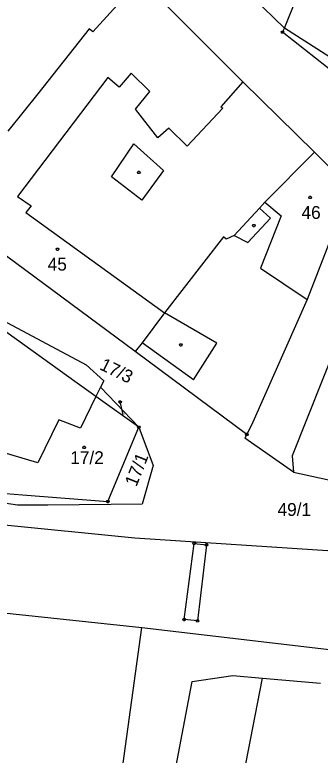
# Model space of a CAD drawing. Extents: x -634640 to -629202, y -1196156 to -1190068.
# Drawn here: x -631402.3 to -631362, y -1192622.8 to -1192525.3 of the extents above; entities that cross this region are included whole.
import ezdxf

# ---------------------------------------------------------------- set-up
doc = ezdxf.new("R2010")
doc.units = 0
for name, color, linetype in [('Vrstva 1', 7, 'Continuous'), ('Vrstva 2', 7, 'Continuous'), ('Vrstva 3', 7, 'Continuous'), ('Vrstva 4', 7, 'Continuous'), ('Vrstva 5', 7, 'Continuous'), ('Vrstva 7', 7, 'Continuous'), ('Vrstva 8', 7, 'Continuous')]:
    doc.layers.add(name, color=color, linetype=linetype)

msp = doc.modelspace()

# ---------------------------------------------------------------- linework, layer by layer
at = {"layer": 'Vrstva 1'}
for p, q in [((-631366.72, -1192527.02), (-631363.92, -1192519.95)), ((-631385.7, -1192520.6), (-631391.98, -1192527.48)), ((-631385.7, -1192520.6), (-631372.23, -1192534.1)), ((-631366.72, -1192527.02), (-631370.95, -1192522.92)), ((-631392.47, -1192527.12), (-631399.24, -1192535.68)), ((-631391.98, -1192527.48), (-631392.47, -1192527.12)), ((-631360.28, -1192531.15), (-631366.72, -1192527.02)), ((-631372.23, -1192534.1), (-631362.77, -1192543.35)), ((-631399.24, -1192535.68), (-631403.21, -1192540.6)), ((-631362.77, -1192543.35), (-631369.31, -1192549.91)), ((-631362.77, -1192543.35), (-631358.09, -1192548.08)), ((-631358.09, -1192548.08), (-631363.74, -1192562.75)), ((-631369.31, -1192549.91), (-631370.03, -1192550.7)), ((-631370.03, -1192550.7), (-631373.35, -1192554.34)), ((-631386.43, -1192569.6), (-631410.65, -1192551.66)), ((-631374.79, -1192554.5), (-631382.54, -1192564.5)), ((-631374.41, -1192554.8), (-631374.79, -1192554.5)), ((-631373.35, -1192554.34), (-631374.41, -1192554.8)), ((-631363.74, -1192562.75), (-631370.89, -1192578.9)), ((-631394.07, -1192573.75), (-631408.55, -1192563.37)), ((-631408.43, -1192563.08), (-631392.89, -1192571.37)), ((-631357.63, -1192562.92), (-631365.7, -1192583.34)), ((-631382.54, -1192564.5), (-631385.51, -1192568.47)), ((-631385.51, -1192568.47), (-631386.43, -1192569.6)), ((-631371.7, -1192580.51), (-631386.43, -1192569.6)), ((-631392.89, -1192571.37), (-631390.56, -1192573.48)), ((-631390.56, -1192573.48), (-631390.99, -1192574.3)), ((-631391.58, -1192575.53), (-631394.07, -1192573.75)), ((-631390.99, -1192574.3), (-631391.58, -1192575.53)), ((-631390.99, -1192574.3), (-631385.93, -1192579.57)), ((-631391.58, -1192575.53), (-631393.63, -1192579.68)), ((-631385.93, -1192579.57), (-631391.58, -1192575.53)), ((-631396.46, -1192578.6), (-631399.25, -1192584.24)), ((-631393.63, -1192579.68), (-631396.46, -1192578.6)), ((-631370.89, -1192578.9), (-631371.7, -1192580.51)), ((-631399.25, -1192584.24), (-631415.08, -1192579.62)), ((-631390.01, -1192589.37), (-631385.93, -1192579.57)), ((-631385.93, -1192579.57), (-631384.02, -1192584.62)), ((-631371.7, -1192580.51), (-631371.96, -1192581.02)), ((-631365.55, -1192585.49), (-631371.96, -1192581.02)), ((-631365.7, -1192583.34), (-631365.55, -1192585.49)), ((-631384.02, -1192584.62), (-631385.48, -1192589.72)), ((-631365.55, -1192585.49), (-631353.37, -1192588.16)), ((-631413.23, -1192587.56), (-631401.28, -1192588.49)), ((-631401.91, -1192589.82), (-631410.57, -1192588.53)), ((-631401.28, -1192588.49), (-631390.01, -1192589.37)), ((-631397.9, -1192589.84), (-631401.91, -1192589.82)), ((-631385.48, -1192589.72), (-631397.9, -1192589.84)), ((-631386.46, -1192594.17), (-631416.15, -1192591.27)), ((-631355.77, -1192596.21), (-631386.46, -1192594.17)), ((-631412.23, -1192603.12), (-631385.52, -1192605.93)), ((-631390.28, -1192640.16), (-631385.52, -1192605.93)), ((-631385.52, -1192605.93), (-631353.37, -1192609.74)), ((-631378.89, -1192613.08), (-631373.54, -1192612.25)), ((-631373.54, -1192612.25), (-631369.61, -1192612.61)), ((-631371.82, -1192623.91), (-631369.61, -1192612.61)), ((-631369.61, -1192612.61), (-631361.99, -1192613.3)), ((-631387.27, -1192657.24), (-631378.89, -1192613.08))]:
    msp.add_line(p, q, dxfattribs=at)
msp.add_lwpolyline([(-631358.1, -1192533.83), (-631358.31, -1192534.41), (-631367, -1192527.54), (-631366.72, -1192527.02)], dxfattribs=at)
at = {"layer": 'Vrstva 3'}
msp.add_lwpolyline([(-631393.03, -1192582.08), (-631392.94, -1192582.23), (-631393.03, -1192582.38), (-631393.21, -1192582.38), (-631393.3, -1192582.23), (-631393.21, -1192582.08), (-631393.03, -1192582.08)], dxfattribs=at)
at = {"layer": 'Vrstva 4'}
for p, q in [((-631390, -1192533.49), (-631401.92, -1192549.18)), ((-631388.51, -1192534.78), (-631390, -1192533.49)), ((-631386.96, -1192532.96), (-631388.51, -1192534.78)), ((-631384.47, -1192535.37), (-631386.96, -1192532.96)), ((-631372.23, -1192534.1), (-631375.11, -1192537.36)), ((-631386.35, -1192537.69), (-631384.47, -1192535.37)), ((-631374.85, -1192537.53), (-631379.54, -1192542.57)), ((-631375.11, -1192537.36), (-631374.85, -1192537.53)), ((-631383.42, -1192541.44), (-631386.35, -1192537.69)), ((-631381.97, -1192540.17), (-631383.42, -1192541.44)), ((-631379.54, -1192542.57), (-631381.97, -1192540.17)), ((-631389.53, -1192546.59), (-631386.6, -1192542.24)), ((-631386.6, -1192542.24), (-631382.69, -1192545.74)), ((-631382.69, -1192545.74), (-631385.52, -1192549.66)), ((-631385.52, -1192549.66), (-631389.53, -1192546.59)), ((-631401.92, -1192549.18), (-631400.12, -1192550.42)), ((-631369.31, -1192549.91), (-631367.17, -1192551.71)), ((-631400.12, -1192550.42), (-631400.82, -1192551.28)), ((-631368.57, -1192552.03), (-631370.03, -1192550.7)), ((-631400.82, -1192551.28), (-631382.54, -1192564.5)), ((-631371.58, -1192555.25), (-631368.57, -1192552.03)), ((-631367.17, -1192551.71), (-631369.91, -1192558.62)), ((-631373.35, -1192554.34), (-631371.58, -1192555.25)), ((-631369.91, -1192558.62), (-631363.74, -1192562.75)), ((-631375.63, -1192568.49), (-631382.54, -1192564.5)), ((-631378.72, -1192573.34), (-631385.51, -1192568.47)), ((-631378.72, -1192573.34), (-631375.63, -1192568.49)), ((-631379.97, -1192604.91), (-631378.64, -1192594.87)), ((-631378.64, -1192594.87), (-631377.02, -1192595.05)), ((-631377.02, -1192595.05), (-631378.21, -1192605.07)), ((-631378.21, -1192605.07), (-631379.97, -1192604.91))]:
    msp.add_line(p, q, dxfattribs=at)
for points in [[(-631378.515, -1192594.993), (-631378.683, -1192595.045), (-631378.807, -1192594.922), (-631378.765, -1192594.747), (-631378.597, -1192594.695), (-631378.473, -1192594.818), (-631378.515, -1192594.993)], [(-631377.104, -1192595.204), (-631377.2, -1192595.057), (-631377.116, -1192594.904), (-631376.936, -1192594.896), (-631376.84, -1192595.043), (-631376.924, -1192595.196), (-631377.104, -1192595.204)], [(-631379.885, -1192604.757), (-631379.79, -1192604.904), (-631379.875, -1192605.057), (-631380.055, -1192605.063), (-631380.15, -1192604.916), (-631380.065, -1192604.763), (-631379.885, -1192604.757)], [(-631378.31, -1192604.926), (-631378.136, -1192604.906), (-631378.036, -1192605.05), (-631378.11, -1192605.214), (-631378.284, -1192605.234), (-631378.384, -1192605.09), (-631378.31, -1192604.926)]]:
    msp.add_lwpolyline(points, dxfattribs=at)
at = {"layer": 'Vrstva 5'}
for points in [[(-631385.83, -1192545.86), (-631385.74, -1192546.01), (-631385.83, -1192546.16), (-631386.01, -1192546.16), (-631386.1, -1192546.01), (-631386.01, -1192545.86), (-631385.83, -1192545.86)], [(-631363.26, -1192549.16), (-631363.17, -1192549.31), (-631363.26, -1192549.46), (-631363.44, -1192549.46), (-631363.53, -1192549.31), (-631363.44, -1192549.16), (-631363.26, -1192549.16)], [(-631370.68, -1192552.86), (-631370.59, -1192553.01), (-631370.68, -1192553.16), (-631370.86, -1192553.16), (-631370.95, -1192553.01), (-631370.86, -1192552.86), (-631370.68, -1192552.86)], [(-631396.56, -1192555.98), (-631396.47, -1192556.13), (-631396.56, -1192556.28), (-631396.74, -1192556.28), (-631396.83, -1192556.13), (-631396.74, -1192555.98), (-631396.56, -1192555.98)], [(-631380.32, -1192568.59), (-631380.23, -1192568.74), (-631380.32, -1192568.89), (-631380.5, -1192568.89), (-631380.59, -1192568.74), (-631380.5, -1192568.59), (-631380.32, -1192568.59)]]:
    msp.add_lwpolyline(points, dxfattribs=at)
at = {"layer": 'Vrstva 7'}
msp.add_line((-631388.01, -1192577.9), (-631388.38, -1192576.24), dxfattribs=at)
msp.add_lwpolyline([(-631388.325, -1192576.074), (-631388.204, -1192576.201), (-631388.26, -1192576.367), (-631388.435, -1192576.406), (-631388.556, -1192576.279), (-631388.5, -1192576.113), (-631388.325, -1192576.074)], dxfattribs=at)
at = {"layer": 'Vrstva 8'}
for points in [[(-631366.91, -1192527.39), (-631366.82, -1192527.54), (-631366.91, -1192527.69), (-631367.09, -1192527.69), (-631367.18, -1192527.54), (-631367.09, -1192527.39), (-631366.91, -1192527.39)], [(-631385.84, -1192579.42), (-631385.75, -1192579.57), (-631385.84, -1192579.72), (-631386.02, -1192579.72), (-631386.11, -1192579.57), (-631386.02, -1192579.42), (-631385.84, -1192579.42)], [(-631371.61, -1192580.36), (-631371.52, -1192580.51), (-631371.61, -1192580.66), (-631371.79, -1192580.66), (-631371.88, -1192580.51), (-631371.79, -1192580.36), (-631371.61, -1192580.36)], [(-631389.92, -1192589.22), (-631389.83, -1192589.37), (-631389.92, -1192589.52), (-631390.1, -1192589.52), (-631390.19, -1192589.37), (-631390.1, -1192589.22), (-631389.92, -1192589.22)]]:
    msp.add_lwpolyline(points, dxfattribs=at)

# ---------------------------------------------------------------- texts
at = {"layer": 'Vrstva 2'}
for s, height, p in [('46', 1.7, (-631364.493, -1192552.14)), ('45', 1.7, (-631397.943, -1192558.94)), ('17/3', 0.1, (-631387.987, -1192577.9)), ('17/2', 1.7, (-631394.967, -1192584.43)), ('49/1', 1.7, (-631367.653, -1192591.26))]:
    msp.add_text(s, height=height, dxfattribs=at).set_placement(p)
msp.add_text('17/1', height=1.7, rotation=68.23927, dxfattribs=at).set_placement((-631386.254, -1192587.495))
at = {"layer": 'Vrstva 7'}
msp.add_text('17/3', height=1.7, rotation=333.74792, dxfattribs=at).set_placement((-631391.219, -1192571.897))

doc.saveas('drawing.dxf')
